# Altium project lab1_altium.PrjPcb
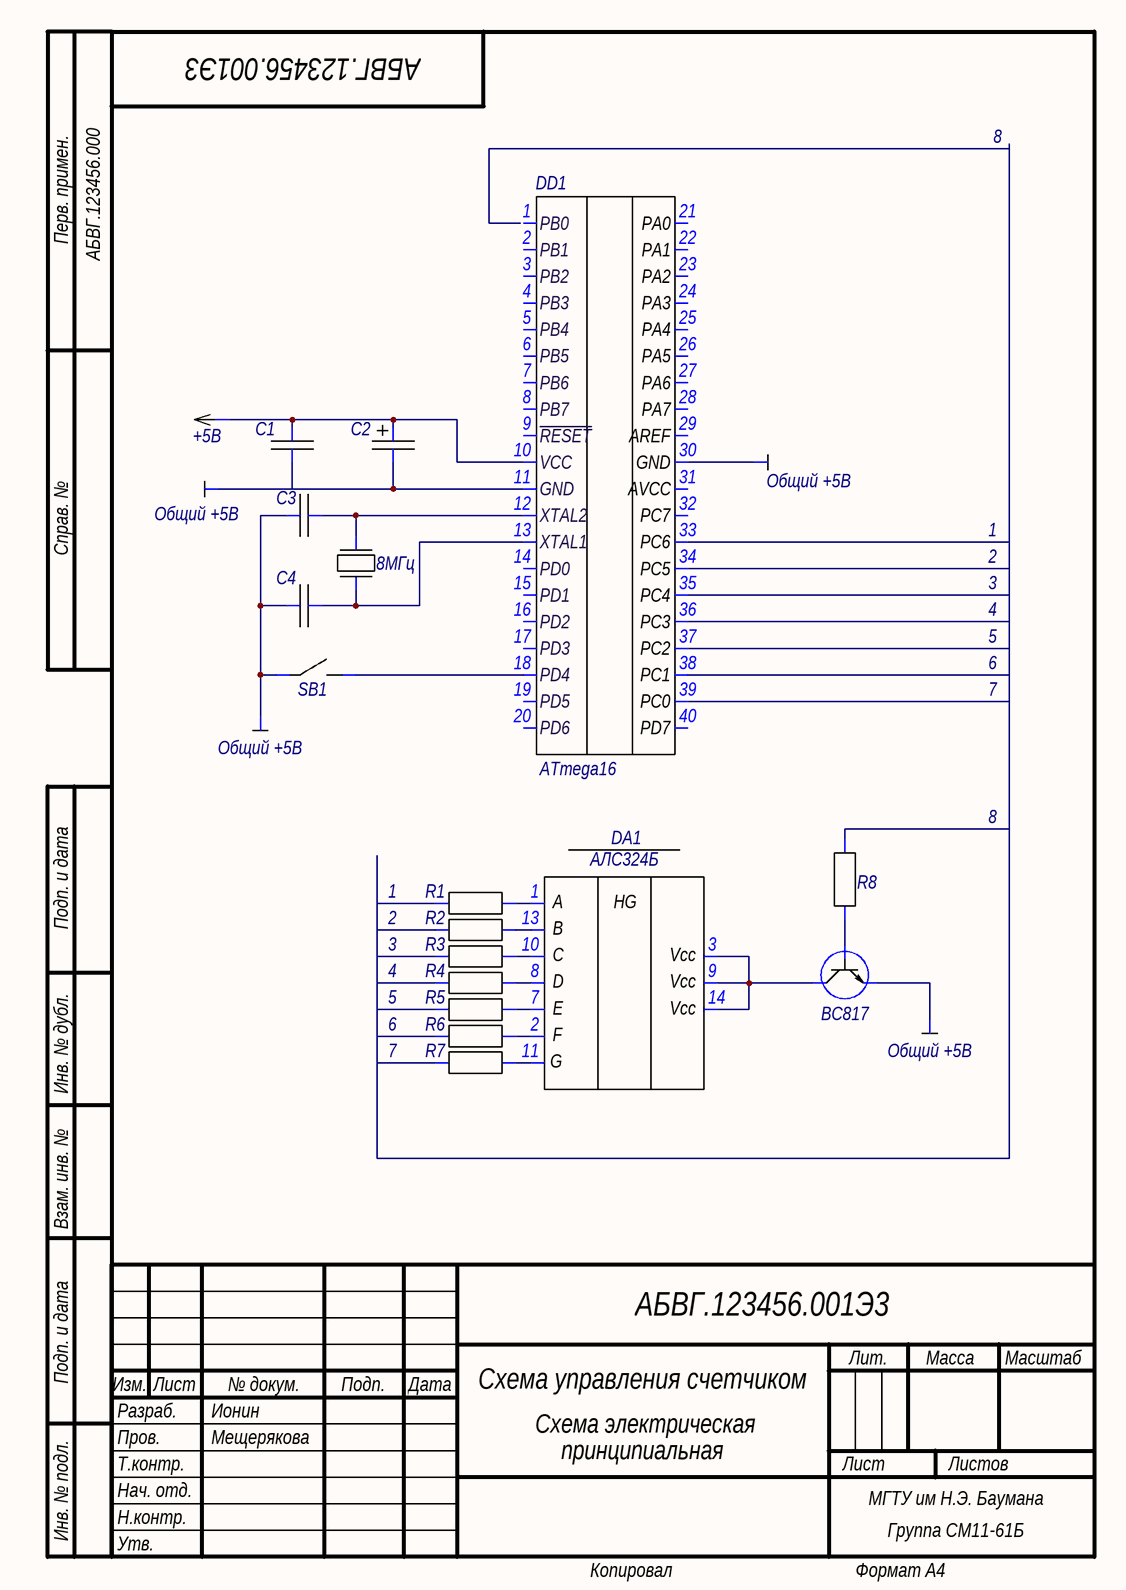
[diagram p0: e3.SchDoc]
1 sheet, 22 parts. Net scope: global (net labels, ports and power ports of the same name join across sheets).

## Sheet e3.SchDoc
size custom portrait; Address1: Address1; Address2: Address2; Address3: Address3; Address4: Address4; SheetNumber: 1; SheetTotal: 1; Scale: 1:1; Разраб.: Иванов; Обозначение документа: АБВГ.123456.001Э3; Пров.: Петров; Утв.: Сидоров; Наименование организации: ОАО "Ваша фирма"; Перв. применение: АБВГ.123456.000; Наименование изделия 1: Плата; Наименование изделия 2: Схема электрическая; Наименование изделия 3: принципиальная; Нач. отд.: Нач. отд.; Фамилия нач. отд.: Сидоров

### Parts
(Parts that share a designator on the sheet are numbered #1, #2 ... from top to bottom, then left to right.)
8МГц  8МГц
+5В  +5В
BC817  transistor  (value not drawn)
C1  Capacitor  (value not drawn)
C2  Capacitor +  (value not drawn)
C3  Capacitor  (value not drawn)
C4  Capacitor  (value not drawn)
DA1  АЛС324Б
DD1  ATmega16
R1  Resistor  (value not drawn)
R2  Resistor  (value not drawn)
R3  Resistor  (value not drawn)
R4  Resistor  (value not drawn)
R5  Resistor  (value not drawn)
R6  Resistor  (value not drawn)
R7  Resistor  (value not drawn)
R8  Resistor  (value not drawn)
SB1  Ключ  (value not drawn)
Общий_+5В  Общий +5В
Общий_+?#1  Общий +5В
Общий_+?#2  Общий +5В
Общий_+?#3  Общий +5В

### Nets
Net8МГц_1: 8МГц.1 C4.2 DD1.13(XTAL1)
Net8МГц_2: 8МГц.2 C3.2 DD1.12(XTAL2)
Net+5В_1: +5В.1 C1.2 C2.2 DD1.10(VCC)
NetBC817_1: BC817.1 R8.1
NetBC817_2: BC817.2 DA1.3 DA1.9 DA1.14
NetBC817_2: BC817.2 Общий_+?#3.1  [a separate net that carries the same name]
NetC1_1: C1.1 C2.1 DD1.11(GND) Общий_+5В.1
NetC3_1: C3.1 C4.1 SB1.1 Общий_+?#2.1
NetDA1_1: DA1.1 R1.2
NetDA1_2: DA1.2 R6.2
NetDA1_7: DA1.7 R5.2
NetDA1_8: DA1.8 R4.2
NetDA1_10: DA1.10 R3.2
NetDA1_11: DA1.11 R7.2
NetDA1_13: DA1.13 R2.2
NetDD1_18: DD1.18(PD4) SB1.2
NetDD1_30: DD1.30(GND) Общий_+?#1.1

Not connected (* = marked no-connect by the designer): DD1 1(PB0) 2(PB1) 3(PB2) 4(PB3) 5(PB4) 6(PB5) 7(PB6) 8(PB7) 9(~{RESET}) 14(PD0) 15(PD1) 16(PD2) 17(PD3) 19(PD5) 20(PD6) 21(PA0) 22(PA1) 23(PA2) 24(PA3) 25(PA4) 26(PA5) 27(PA6) 28(PA7) 29(AREF) 31(AVCC) 32(PC7) 33(PC6) 34(PC5) 35(PC4) 36(PC3) 37(PC2) 38(PC1) 39(PC0) 40(PD7); R1 1; R2 1; R3 1; R4 1; R5 1; R6 1; R7 1; R8 2

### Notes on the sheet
- 8
- Перв. примен.
- Справ. №
- 1
- 2
- 3
- 4
- 5
- 6
- 7
- Подп. и дата
- Инв. № дубл.
- Взам. инв. №
- Разраб.
- Изм.
- Лист
- Ионин
- № докум.
- Подп.
- Дата
- Cхема управления счетчиком
- Лит.
- Масса
- Масштаб
- Пров.
- Т.контр.
- Мещерякова
- Листов
- Инв. № подл.
- Утв.
- Н.контр.
- МГТУ им Н.Э. Баумана
- Группа СМ11-61Б
- Копировал
- Формат А4

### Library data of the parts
8МГц = кварцевый резонатор
+5В = питание
Общий_+5В Общий_+?#1-Общий_+?#3 = земля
